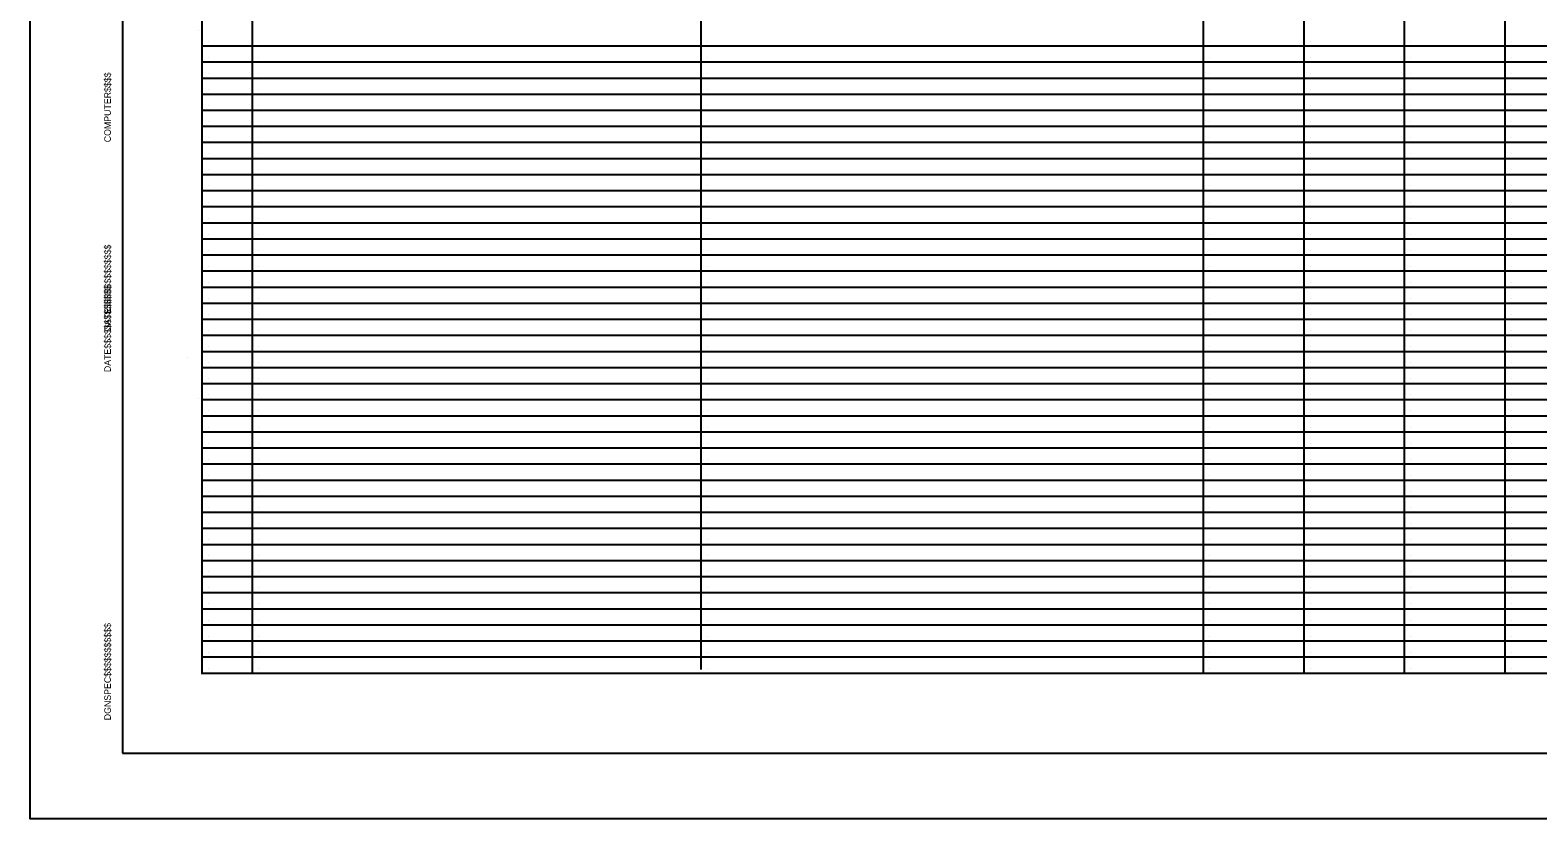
# Model space of a CAD drawing. Extents: x 0 to 3.48, y 0 to 2.25.
# Drawn here: x 0 to 1.913, y 0 to 1 of the extents above; entities that cross this region are included whole.
import ezdxf

# ---------------------------------------------------------------- set-up
doc = ezdxf.new("R2010")
doc.units = 0
for name, color, linetype in [('Border Active Points', 7, 'Continuous'), ('Border Line', 7, 'Continuous'), ('Border Organizer Shape', 7, 'Continuous')]:
    doc.layers.add(name, color=color, linetype=linetype)

msp = doc.modelspace()

# ---------------------------------------------------------------- linework, layer by layer
at = {"layer": 'Border Active Points'}
for p, q in [((0.2142, 1), (0.2142, 1)), ((0.2262, 0.9865), (0.2262, 0.9865)), ((0.29, 0.9865), (0.29, 0.9865)), ((0.8595, 0.9865), (0.8595, 0.9865)), ((1.497, 0.9865), (1.497, 0.9865)), ((1.6245, 0.9865), (1.6245, 0.9865)), ((1.752, 0.9865), (1.752, 0.9865)), ((1.8795, 0.9865), (1.8795, 0.9865)), ((0.2262, 0.9661), (0.2262, 0.9661)), ((0.29, 0.9661), (0.29, 0.9661)), ((0.8595, 0.9661), (0.8595, 0.9661)), ((1.497, 0.9661), (1.497, 0.9661)), ((1.6245, 0.9661), (1.6245, 0.9661)), ((1.752, 0.9661), (1.752, 0.9661)), ((1.8795, 0.9661), (1.8795, 0.9661)), ((0.2262, 0.9457), (0.2262, 0.9457)), ((0.29, 0.9457), (0.29, 0.9457)), ((0.8595, 0.9457), (0.8595, 0.9457)), ((1.497, 0.9457), (1.497, 0.9457)), ((1.6245, 0.9457), (1.6245, 0.9457)), ((1.752, 0.9457), (1.752, 0.9457)), ((1.8795, 0.9457), (1.8795, 0.9457)), ((0.2262, 0.9253), (0.2262, 0.9253)), ((0.29, 0.9253), (0.29, 0.9253)), ((0.8595, 0.9253), (0.8595, 0.9253)), ((1.497, 0.9253), (1.497, 0.9253)), ((1.6245, 0.9253), (1.6245, 0.9253)), ((1.752, 0.9253), (1.752, 0.9253)), ((1.8795, 0.9253), (1.8795, 0.9253)), ((0.2262, 0.9049), (0.2262, 0.9049)), ((0.29, 0.9049), (0.29, 0.9049)), ((0.8595, 0.9049), (0.8595, 0.9049)), ((1.497, 0.9049), (1.497, 0.9049)), ((1.6245, 0.9049), (1.6245, 0.9049)), ((1.752, 0.9049), (1.752, 0.9049)), ((1.8795, 0.9049), (1.8795, 0.9049)), ((0.2262, 0.8845), (0.2262, 0.8845)), ((0.29, 0.8845), (0.29, 0.8845)), ((0.8595, 0.8845), (0.8595, 0.8845)), ((1.497, 0.8845), (1.497, 0.8845)), ((1.6245, 0.8845), (1.6245, 0.8845)), ((1.752, 0.8845), (1.752, 0.8845)), ((1.8795, 0.8845), (1.8795, 0.8845)), ((0.2262, 0.8641), (0.2262, 0.8641)), ((0.29, 0.8641), (0.29, 0.8641)), ((0.8595, 0.8641), (0.8595, 0.8641)), ((1.497, 0.8641), (1.497, 0.8641)), ((1.6245, 0.8641), (1.6245, 0.8641)), ((1.752, 0.8641), (1.752, 0.8641)), ((1.8795, 0.8641), (1.8795, 0.8641)), ((0.2262, 0.8437), (0.2262, 0.8437)), ((0.29, 0.8437), (0.29, 0.8437)), ((0.8595, 0.8437), (0.8595, 0.8437)), ((1.497, 0.8437), (1.497, 0.8437)), ((1.6245, 0.8437), (1.6245, 0.8437)), ((1.752, 0.8437), (1.752, 0.8437)), ((1.8795, 0.8437), (1.8795, 0.8437)), ((0.2262, 0.8233), (0.2262, 0.8233)), ((0.29, 0.8233), (0.29, 0.8233)), ((0.8595, 0.8233), (0.8595, 0.8233)), ((1.497, 0.8233), (1.497, 0.8233)), ((1.6245, 0.8233), (1.6245, 0.8233)), ((1.752, 0.8233), (1.752, 0.8233)), ((1.8795, 0.8233), (1.8795, 0.8233)), ((0.2262, 0.8029), (0.2262, 0.8029)), ((0.29, 0.8029), (0.29, 0.8029)), ((0.8595, 0.8029), (0.8595, 0.8029)), ((1.497, 0.8029), (1.497, 0.8029)), ((1.6245, 0.8029), (1.6245, 0.8029)), ((1.752, 0.8029), (1.752, 0.8029)), ((1.8795, 0.8029), (1.8795, 0.8029)), ((0.2262, 0.7825), (0.2262, 0.7825)), ((0.29, 0.7825), (0.29, 0.7825)), ((0.8595, 0.7825), (0.8595, 0.7825)), ((1.497, 0.7825), (1.497, 0.7825)), ((1.6245, 0.7825), (1.6245, 0.7825)), ((1.752, 0.7825), (1.752, 0.7825)), ((1.8795, 0.7825), (1.8795, 0.7825)), ((0.2262, 0.7621), (0.2262, 0.7621)), ((0.29, 0.7621), (0.29, 0.7621)), ((0.8595, 0.7621), (0.8595, 0.7621)), ((1.497, 0.7621), (1.497, 0.7621)), ((1.6245, 0.7621), (1.6245, 0.7621)), ((1.752, 0.7621), (1.752, 0.7621)), ((1.8795, 0.7621), (1.8795, 0.7621)), ((0.2262, 0.7417), (0.2262, 0.7417)), ((0.29, 0.7417), (0.29, 0.7417)), ((0.8595, 0.7417), (0.8595, 0.7417)), ((1.497, 0.7417), (1.497, 0.7417)), ((1.6245, 0.7417), (1.6245, 0.7417)), ((1.752, 0.7417), (1.752, 0.7417)), ((1.8795, 0.7417), (1.8795, 0.7417)), ((0.2262, 0.7213), (0.2262, 0.7213)), ((0.29, 0.7213), (0.29, 0.7213)), ((0.8595, 0.7213), (0.8595, 0.7213)), ((1.497, 0.7213), (1.497, 0.7213)), ((1.6245, 0.7213), (1.6245, 0.7213)), ((1.752, 0.7213), (1.752, 0.7213)), ((1.8795, 0.7213), (1.8795, 0.7213)), ((0.2262, 0.7009), (0.2262, 0.7009)), ((0.29, 0.7009), (0.29, 0.7009)), ((0.8595, 0.7009), (0.8595, 0.7009)), ((1.497, 0.7009), (1.497, 0.7009)), ((1.6245, 0.7009), (1.6245, 0.7009)), ((1.752, 0.7009), (1.752, 0.7009)), ((1.8795, 0.7009), (1.8795, 0.7009)), ((0.2262, 0.6805), (0.2262, 0.6805)), ((0.29, 0.6805), (0.29, 0.6805)), ((0.8595, 0.6805), (0.8595, 0.6805)), ((1.497, 0.6805), (1.497, 0.6805)), ((1.6245, 0.6805), (1.6245, 0.6805)), ((1.752, 0.6805), (1.752, 0.6805)), ((1.8795, 0.6805), (1.8795, 0.6805)), ((0.2262, 0.6601), (0.2262, 0.6601)), ((0.29, 0.6601), (0.29, 0.6601)), ((0.8595, 0.6601), (0.8595, 0.6601)), ((1.497, 0.6601), (1.497, 0.6601)), ((1.6245, 0.6601), (1.6245, 0.6601)), ((1.752, 0.6601), (1.752, 0.6601)), ((1.8795, 0.6601), (1.8795, 0.6601)), ((0.2262, 0.6397), (0.2262, 0.6397)), ((0.29, 0.6397), (0.29, 0.6397)), ((0.8595, 0.6397), (0.8595, 0.6397)), ((1.497, 0.6397), (1.497, 0.6397)), ((1.6245, 0.6397), (1.6245, 0.6397)), ((1.752, 0.6397), (1.752, 0.6397)), ((1.8795, 0.6397), (1.8795, 0.6397)), ((0.2262, 0.6193), (0.2262, 0.6193)), ((0.29, 0.6193), (0.29, 0.6193)), ((0.8595, 0.6193), (0.8595, 0.6193)), ((1.497, 0.6193), (1.497, 0.6193)), ((1.6245, 0.6193), (1.6245, 0.6193)), ((1.752, 0.6193), (1.752, 0.6193)), ((1.8795, 0.6193), (1.8795, 0.6193)), ((0.2262, 0.5989), (0.2262, 0.5989)), ((0.29, 0.5989), (0.29, 0.5989)), ((0.8595, 0.5989), (0.8595, 0.5989)), ((1.497, 0.5989), (1.497, 0.5989)), ((1.6245, 0.5989), (1.6245, 0.5989)), ((1.752, 0.5989), (1.752, 0.5989)), ((1.8795, 0.5989), (1.8795, 0.5989)), ((0.2002, 0.5849), (0.2002, 0.5849)), ((0.2262, 0.5786), (0.2262, 0.5786)), ((0.29, 0.5786), (0.29, 0.5786)), ((0.8595, 0.5786), (0.8595, 0.5786)), ((1.497, 0.5786), (1.497, 0.5786)), ((1.6245, 0.5786), (1.6245, 0.5786)), ((1.752, 0.5786), (1.752, 0.5786)), ((1.8795, 0.5786), (1.8795, 0.5786)), ((0.2262, 0.5582), (0.2262, 0.5582)), ((0.29, 0.5582), (0.29, 0.5582)), ((0.8595, 0.5582), (0.8595, 0.5582)), ((1.497, 0.5582), (1.497, 0.5582)), ((1.6245, 0.5582), (1.6245, 0.5582)), ((1.752, 0.5582), (1.752, 0.5582)), ((1.8795, 0.5582), (1.8795, 0.5582)), ((0.2262, 0.5378), (0.2262, 0.5378)), ((0.29, 0.5378), (0.29, 0.5378)), ((0.8595, 0.5378), (0.8595, 0.5378)), ((1.497, 0.5378), (1.497, 0.5378)), ((1.6245, 0.5378), (1.6245, 0.5378)), ((1.752, 0.5378), (1.752, 0.5378)), ((1.8795, 0.5378), (1.8795, 0.5378)), ((0.2142, 0.5335), (0.2142, 0.5335)), ((0.2262, 0.5174), (0.2262, 0.5174)), ((0.29, 0.5174), (0.29, 0.5174)), ((0.8595, 0.5174), (0.8595, 0.5174)), ((1.497, 0.5174), (1.497, 0.5174)), ((1.6245, 0.5174), (1.6245, 0.5174)), ((1.752, 0.5174), (1.752, 0.5174)), ((1.8795, 0.5174), (1.8795, 0.5174)), ((0.2262, 0.497), (0.2262, 0.497)), ((0.29, 0.497), (0.29, 0.497)), ((0.8595, 0.497), (0.8595, 0.497)), ((1.497, 0.497), (1.497, 0.497)), ((1.6245, 0.497), (1.6245, 0.497)), ((1.752, 0.497), (1.752, 0.497)), ((1.8795, 0.497), (1.8795, 0.497)), ((0.2262, 0.4766), (0.2262, 0.4766)), ((0.29, 0.4766), (0.29, 0.4766)), ((0.8595, 0.4766), (0.8595, 0.4766)), ((1.497, 0.4766), (1.497, 0.4766)), ((1.6245, 0.4766), (1.6245, 0.4766)), ((1.752, 0.4766), (1.752, 0.4766)), ((1.8795, 0.4766), (1.8795, 0.4766)), ((0.2262, 0.4562), (0.2262, 0.4562)), ((0.29, 0.4562), (0.29, 0.4562)), ((0.8595, 0.4562), (0.8595, 0.4562)), ((1.497, 0.4562), (1.497, 0.4562)), ((1.6245, 0.4562), (1.6245, 0.4562)), ((1.752, 0.4562), (1.752, 0.4562)), ((1.8795, 0.4562), (1.8795, 0.4562)), ((0.2262, 0.4358), (0.2262, 0.4358)), ((0.29, 0.4358), (0.29, 0.4358)), ((0.8595, 0.4358), (0.8595, 0.4358)), ((1.497, 0.4358), (1.497, 0.4358)), ((1.6245, 0.4358), (1.6245, 0.4358)), ((1.752, 0.4358), (1.752, 0.4358)), ((1.8795, 0.4358), (1.8795, 0.4358)), ((0.2262, 0.4154), (0.2262, 0.4154)), ((0.29, 0.4154), (0.29, 0.4154)), ((0.8595, 0.4154), (0.8595, 0.4154)), ((1.497, 0.4154), (1.497, 0.4154)), ((1.6245, 0.4154), (1.6245, 0.4154)), ((1.752, 0.4154), (1.752, 0.4154)), ((1.8795, 0.4154), (1.8795, 0.4154)), ((0.2262, 0.395), (0.2262, 0.395)), ((0.29, 0.395), (0.29, 0.395)), ((0.8595, 0.395), (0.8595, 0.395)), ((1.497, 0.395), (1.497, 0.395)), ((1.6245, 0.395), (1.6245, 0.395)), ((1.752, 0.395), (1.752, 0.395)), ((1.8795, 0.395), (1.8795, 0.395)), ((0.2262, 0.3746), (0.2262, 0.3746)), ((0.29, 0.3746), (0.29, 0.3746)), ((0.8595, 0.3746), (0.8595, 0.3746)), ((1.497, 0.3746), (1.497, 0.3746)), ((1.6245, 0.3746), (1.6245, 0.3746)), ((1.752, 0.3746), (1.752, 0.3746)), ((1.8795, 0.3746), (1.8795, 0.3746)), ((0.2262, 0.3542), (0.2262, 0.3542)), ((0.29, 0.3542), (0.29, 0.3542)), ((0.8595, 0.3542), (0.8595, 0.3542)), ((1.497, 0.3542), (1.497, 0.3542)), ((1.6245, 0.3542), (1.6245, 0.3542)), ((1.752, 0.3542), (1.752, 0.3542)), ((1.8795, 0.3542), (1.8795, 0.3542)), ((0.2262, 0.3338), (0.2262, 0.3338)), ((0.29, 0.3338), (0.29, 0.3338)), ((0.8595, 0.3338), (0.8595, 0.3338)), ((1.497, 0.3338), (1.497, 0.3338)), ((1.6245, 0.3338), (1.6245, 0.3338)), ((1.752, 0.3338), (1.752, 0.3338)), ((1.8795, 0.3338), (1.8795, 0.3338)), ((0.2262, 0.3134), (0.2262, 0.3134)), ((0.29, 0.3134), (0.29, 0.3134)), ((0.8595, 0.3134), (0.8595, 0.3134)), ((1.497, 0.3134), (1.497, 0.3134)), ((1.6245, 0.3134), (1.6245, 0.3134)), ((1.752, 0.3134), (1.752, 0.3134)), ((1.8795, 0.3134), (1.8795, 0.3134)), ((0.2262, 0.293), (0.2262, 0.293)), ((0.29, 0.293), (0.29, 0.293)), ((0.8595, 0.293), (0.8595, 0.293)), ((1.497, 0.293), (1.497, 0.293)), ((1.6245, 0.293), (1.6245, 0.293)), ((1.752, 0.293), (1.752, 0.293)), ((1.8795, 0.293), (1.8795, 0.293)), ((0.2262, 0.2726), (0.2262, 0.2726)), ((0.29, 0.2726), (0.29, 0.2726)), ((0.8595, 0.2726), (0.8595, 0.2726)), ((1.497, 0.2726), (1.497, 0.2726)), ((1.6245, 0.2726), (1.6245, 0.2726)), ((1.752, 0.2726), (1.752, 0.2726)), ((1.8795, 0.2726), (1.8795, 0.2726)), ((0.2262, 0.2522), (0.2262, 0.2522)), ((0.29, 0.2522), (0.29, 0.2522)), ((0.8595, 0.2522), (0.8595, 0.2522)), ((1.497, 0.2522), (1.497, 0.2522)), ((1.6245, 0.2522), (1.6245, 0.2522)), ((1.752, 0.2522), (1.752, 0.2522)), ((1.8795, 0.2522), (1.8795, 0.2522)), ((0.2262, 0.2318), (0.2262, 0.2318)), ((0.29, 0.2318), (0.29, 0.2318)), ((0.8595, 0.2318), (0.8595, 0.2318)), ((1.497, 0.2318), (1.497, 0.2318)), ((1.6245, 0.2318), (1.6245, 0.2318)), ((1.752, 0.2318), (1.752, 0.2318)), ((1.8795, 0.2318), (1.8795, 0.2318)), ((0.2262, 0.2114), (0.2262, 0.2114)), ((0.29, 0.2114), (0.29, 0.2114)), ((0.8595, 0.2114), (0.8595, 0.2114)), ((1.497, 0.2114), (1.497, 0.2114)), ((1.6245, 0.2114), (1.6245, 0.2114)), ((1.752, 0.2114), (1.752, 0.2114)), ((1.8795, 0.2114), (1.8795, 0.2114)), ((0.2262, 0.191), (0.2262, 0.191)), ((0.29, 0.191), (0.29, 0.191)), ((0.8595, 0.191), (0.8595, 0.191)), ((1.497, 0.191), (1.497, 0.191)), ((1.6245, 0.191), (1.6245, 0.191)), ((1.752, 0.191), (1.752, 0.191)), ((1.8795, 0.191), (1.8795, 0.191))]:
    msp.add_line(p, q, dxfattribs=at)
at = {"layer": 'Border Line'}
for p, q in [((0.2177, 1.681), (0.2177, 0.185)), ((0.2815, 1.6555), (0.2815, 0.185)), ((0.851, 1.6555), (0.851, 0.1893)), ((1.4885, 1.6555), (1.4885, 0.185)), ((1.616, 1.6555), (1.616, 0.185)), ((1.7435, 1.6555), (1.7435, 0.185)), ((1.871, 1.6555), (1.871, 0.185)), ((0.2177, 0.9806), (2.6827, 0.9806)), ((0.2177, 0.9602), (2.6827, 0.9602)), ((0.2177, 0.9398), (2.6827, 0.9398)), ((0.2177, 0.9194), (2.6827, 0.9194)), ((0.2177, 0.899), (2.6827, 0.899)), ((0.2177, 0.8786), (2.6827, 0.8786)), ((0.2177, 0.8582), (2.6827, 0.8582)), ((0.2177, 0.8378), (2.6827, 0.8378)), ((0.2177, 0.8174), (2.6827, 0.8174)), ((0.2177, 0.797), (2.6827, 0.797)), ((0.2177, 0.7766), (2.6827, 0.7766)), ((0.2177, 0.7562), (2.6827, 0.7562)), ((0.2177, 0.7358), (2.6827, 0.7358)), ((0.2177, 0.7154), (2.6827, 0.7154)), ((0.2177, 0.695), (2.6827, 0.695)), ((0.2177, 0.6746), (2.6827, 0.6746)), ((0.2177, 0.6542), (2.6827, 0.6542)), ((0.2177, 0.6338), (2.6827, 0.6338)), ((0.2177, 0.6134), (2.6827, 0.6134)), ((0.2177, 0.593), (2.6827, 0.593)), ((0.2177, 0.5726), (2.6827, 0.5726)), ((0.2177, 0.5522), (2.6827, 0.5522)), ((0.2177, 0.5318), (2.6827, 0.5318)), ((0.2177, 0.5114), (2.6827, 0.5114)), ((0.2177, 0.491), (2.6827, 0.491)), ((0.2177, 0.4706), (2.6827, 0.4706)), ((0.2177, 0.4502), (2.6827, 0.4502)), ((0.2177, 0.4298), (2.6827, 0.4298)), ((0.2177, 0.4094), (2.6827, 0.4094)), ((0.2177, 0.389), (2.6827, 0.389)), ((0.2177, 0.3686), (2.6827, 0.3686)), ((0.2177, 0.3482), (2.6827, 0.3482)), ((0.2177, 0.3278), (2.6827, 0.3278)), ((0.2177, 0.3074), (2.6827, 0.3074)), ((0.2177, 0.287), (2.6827, 0.287)), ((0.2177, 0.2666), (2.6827, 0.2666)), ((0.2177, 0.2462), (2.6827, 0.2462)), ((0.2177, 0.2258), (2.6827, 0.2258)), ((0.2177, 0.2054), (2.6827, 0.2054)), ((0.217, 0.185), (2.6827, 0.185))]:
    msp.add_line(p, q, dxfattribs=at)
msp.add_lwpolyline([(0.117, 0.0835), (2.95, 0.0835), (2.95, 1.9165), (0.117, 1.9165)], close=True, dxfattribs=at)
at = {"layer": 'Border Organizer Shape'}
msp.add_lwpolyline([(3, 0), (0, 0), (0, 2), (3, 2)], close=True, dxfattribs=at)

# ---------------------------------------------------------------- texts
at = {"layer": 'Border Line'}
for s, p in [('COMPUTER$$$$', (0.1024, 0.8583)), ('COMPUTER$$$$', (0.1024, 0.8583)), ('COMPUTER$$$$', (0.1024, 0.8583)), ('COMPUTER$$$$', (0.1024, 0.8583)), ('DATE$$$$$$$$$$$$$', (0.1024, 0.6182)), ('DATE$$$$$$$$$$$$$', (0.1024, 0.5667)), ('DATE$$$$$$$$$$$$$', (0.1024, 0.5667)), ('DGNSPEC$$$$$$$$$$$', (0.1024, 0.1251)), ('DGNSPEC$$$$$$$$$$$', (0.1024, 0.1251)), ('DGNSPEC$$$$$$$$$$$', (0.1024, 0.1251))]:
    msp.add_text(s, height=0.00833, rotation=90, dxfattribs=at).set_placement(p)

doc.saveas('drawing.dxf')
